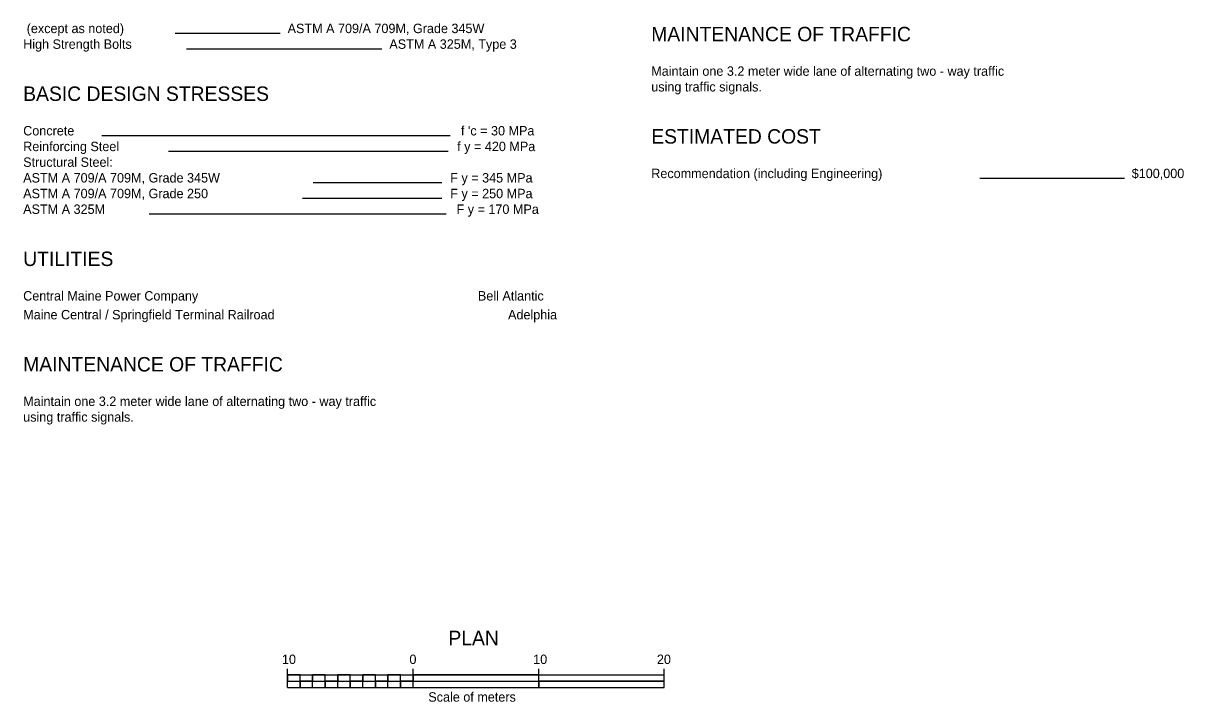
# Model space of a CAD drawing. Extents: x 605371.3 to 605398.1, y 420183.2 to 420214.1.
# Drawn here: x 605390.579 to 605390.9486, y 420198.7766 to 420198.9928 of the extents above; entities that cross this region are included whole.
import ezdxf

# ---------------------------------------------------------------- set-up
doc = ezdxf.new("R2010")
doc.units = 0
doc.layers.add('Fram_Steel', color=7, linetype='Continuous')

msp = doc.modelspace()

# ---------------------------------------------------------------- linework, layer by layer
at = {"layer": 'Fram_Steel'}
for p, q in [((605390.62737, 420198.9896), (605390.66085, 420198.9896)), ((605390.62737, 420198.9896), (605390.66085, 420198.9896)), ((605390.63099, 420198.9846), (605390.6932, 420198.9846)), ((605390.63099, 420198.9846), (605390.6932, 420198.9846)), ((605390.60403, 420198.957), (605390.71501, 420198.957)), ((605390.60403, 420198.957), (605390.71501, 420198.957)), ((605390.62523, 420198.952), (605390.71437, 420198.952)), ((605390.62523, 420198.952), (605390.71437, 420198.952)), ((605390.88363, 420198.9434), (605390.92966, 420198.9434)), ((605390.88363, 420198.9434), (605390.92966, 420198.9434)), ((605390.67134, 420198.942), (605390.71227, 420198.942)), ((605390.67134, 420198.942), (605390.71227, 420198.942)), ((605390.66793, 420198.937), (605390.71227, 420198.937)), ((605390.66793, 420198.937), (605390.71227, 420198.937)), ((605390.61914, 420198.932), (605390.71372, 420198.932)), ((605390.61914, 420198.932), (605390.71372, 420198.932)), ((605390.66316, 420198.78111), (605390.66316, 420198.78711)), ((605390.66316, 420198.78111), (605390.66316, 420198.78711)), ((605390.66716, 420198.78511), (605390.66316, 420198.78511)), ((605390.66316, 420198.78511), (605390.66316, 420198.78311)), ((605390.66316, 420198.78511), (605390.78316, 420198.78511)), ((605390.66316, 420198.78511), (605390.78316, 420198.78511)), ((605390.66716, 420198.78311), (605390.66716, 420198.78511)), ((605390.66716, 420198.78111), (605390.66716, 420198.78511)), ((605390.66716, 420198.78111), (605390.66716, 420198.78511)), ((605390.67516, 420198.78511), (605390.67116, 420198.78511)), ((605390.67116, 420198.78511), (605390.67116, 420198.78311)), ((605390.67116, 420198.78111), (605390.67116, 420198.78511)), ((605390.67116, 420198.78111), (605390.67116, 420198.78511)), ((605390.67516, 420198.78311), (605390.67516, 420198.78511)), ((605390.67516, 420198.78111), (605390.67516, 420198.78511)), ((605390.67516, 420198.78111), (605390.67516, 420198.78511)), ((605390.68316, 420198.78511), (605390.67916, 420198.78511)), ((605390.67916, 420198.78511), (605390.67916, 420198.78311)), ((605390.67916, 420198.78111), (605390.67916, 420198.78511)), ((605390.67916, 420198.78111), (605390.67916, 420198.78511)), ((605390.68316, 420198.78311), (605390.68316, 420198.78511)), ((605390.68316, 420198.78111), (605390.68316, 420198.78511)), ((605390.68316, 420198.78111), (605390.68316, 420198.78511)), ((605390.69116, 420198.78511), (605390.68716, 420198.78511)), ((605390.68716, 420198.78511), (605390.68716, 420198.78311)), ((605390.68716, 420198.78111), (605390.68716, 420198.78511)), ((605390.68716, 420198.78111), (605390.68716, 420198.78511)), ((605390.69116, 420198.78311), (605390.69116, 420198.78511)), ((605390.69116, 420198.78111), (605390.69116, 420198.78511)), ((605390.69116, 420198.78111), (605390.69116, 420198.78511)), ((605390.69916, 420198.78511), (605390.69516, 420198.78511)), ((605390.69516, 420198.78511), (605390.69516, 420198.78311)), ((605390.69516, 420198.78111), (605390.69516, 420198.78511)), ((605390.69516, 420198.78111), (605390.69516, 420198.78511)), ((605390.69916, 420198.78311), (605390.69916, 420198.78511)), ((605390.69916, 420198.78111), (605390.69916, 420198.78511)), ((605390.69916, 420198.78111), (605390.69916, 420198.78511)), ((605390.70316, 420198.78111), (605390.70316, 420198.78711)), ((605390.70316, 420198.78111), (605390.70316, 420198.78711)), ((605390.74316, 420198.78511), (605390.70316, 420198.78511)), ((605390.70316, 420198.78511), (605390.70316, 420198.78311)), ((605390.74316, 420198.78111), (605390.74316, 420198.78711)), ((605390.74316, 420198.78111), (605390.74316, 420198.78711)), ((605390.74316, 420198.78311), (605390.74316, 420198.78511)), ((605390.78316, 420198.78111), (605390.78316, 420198.78711)), ((605390.78316, 420198.78111), (605390.78316, 420198.78711)), ((605390.66316, 420198.78311), (605390.66716, 420198.78311)), ((605390.66316, 420198.78311), (605390.78316, 420198.78311)), ((605390.66316, 420198.78311), (605390.78316, 420198.78311)), ((605390.66316, 420198.78111), (605390.78316, 420198.78111)), ((605390.66316, 420198.78111), (605390.78316, 420198.78111)), ((605390.67116, 420198.78311), (605390.66716, 420198.78311)), ((605390.66716, 420198.78311), (605390.66716, 420198.78111)), ((605390.66716, 420198.78111), (605390.67116, 420198.78111)), ((605390.67116, 420198.78111), (605390.67116, 420198.78311)), ((605390.67116, 420198.78311), (605390.67516, 420198.78311)), ((605390.67916, 420198.78311), (605390.67516, 420198.78311)), ((605390.67516, 420198.78311), (605390.67516, 420198.78111)), ((605390.67516, 420198.78111), (605390.67916, 420198.78111)), ((605390.67916, 420198.78111), (605390.67916, 420198.78311)), ((605390.67916, 420198.78311), (605390.68316, 420198.78311)), ((605390.68716, 420198.78311), (605390.68316, 420198.78311)), ((605390.68316, 420198.78311), (605390.68316, 420198.78111)), ((605390.68316, 420198.78111), (605390.68716, 420198.78111)), ((605390.68716, 420198.78111), (605390.68716, 420198.78311)), ((605390.68716, 420198.78311), (605390.69116, 420198.78311)), ((605390.69516, 420198.78311), (605390.69116, 420198.78311)), ((605390.69116, 420198.78311), (605390.69116, 420198.78111)), ((605390.69116, 420198.78111), (605390.69516, 420198.78111)), ((605390.69516, 420198.78111), (605390.69516, 420198.78311)), ((605390.69516, 420198.78311), (605390.69916, 420198.78311)), ((605390.70316, 420198.78311), (605390.69916, 420198.78311)), ((605390.69916, 420198.78311), (605390.69916, 420198.78111)), ((605390.69916, 420198.78111), (605390.70316, 420198.78111)), ((605390.70316, 420198.78111), (605390.70316, 420198.78311)), ((605390.70316, 420198.78311), (605390.74316, 420198.78311)), ((605390.78316, 420198.78311), (605390.74316, 420198.78311)), ((605390.74316, 420198.78311), (605390.74316, 420198.78111)), ((605390.74316, 420198.78111), (605390.78316, 420198.78111)), ((605390.78316, 420198.78111), (605390.78316, 420198.78311))]:
    msp.add_line(p, q, dxfattribs=at)

# ---------------------------------------------------------------- texts
for s, height, p in [(' (except as noted)', 0.003, (605390.579, 420198.9896)), (' (except as noted)', 0.003, (605390.579, 420198.9896)), ('ASTM A 709/A 709M, Grade 345W', 0.003, (605390.6632, 420198.9896)), ('ASTM A 709/A 709M, Grade 345W', 0.003, (605390.6632, 420198.9896)), ('MAINTENANCE OF TRAFFIC', 0.0045996, (605390.779, 420198.987)), ('MAINTENANCE OF TRAFFIC', 0.0045996, (605390.779, 420198.987)), ('High Strength Bolts', 0.003, (605390.579, 420198.9846)), ('High Strength Bolts', 0.003, (605390.579, 420198.9846)), ('ASTM A 325M, Type 3', 0.003, (605390.6956, 420198.9846)), ('ASTM A 325M, Type 3', 0.003, (605390.6956, 420198.9846)), ('Maintain one 3.2 meter wide lane of alternating two - way traffic', 0.003, (605390.779, 420198.976)), ('Maintain one 3.2 meter wide lane of alternating two - way traffic', 0.003, (605390.779, 420198.976)), ('BASIC DESIGN STRESSES', 0.0045996, (605390.579, 420198.968)), ('BASIC DESIGN STRESSES', 0.0045996, (605390.579, 420198.968)), ('using traffic signals.', 0.003, (605390.779, 420198.971)), ('using traffic signals.', 0.003, (605390.779, 420198.971)), ('Concrete', 0.003, (605390.579, 420198.957)), ('Concrete', 0.003, (605390.579, 420198.957)), ("f 'c = 30 MPa", 0.003, (605390.7184, 420198.957)), ("f 'c = 30 MPa", 0.003, (605390.7184, 420198.957)), ('ESTIMATED COST', 0.0045996, (605390.779, 420198.9544)), ('ESTIMATED COST', 0.0045996, (605390.779, 420198.9544)), ('Reinforcing Steel', 0.003, (605390.579, 420198.952)), ('Reinforcing Steel', 0.003, (605390.579, 420198.952)), ('f y = 420 MPa', 0.003, (605390.7172, 420198.952)), ('f y = 420 MPa', 0.003, (605390.7172, 420198.952)), ('Structural Steel:', 0.003, (605390.579, 420198.947)), ('Structural Steel:', 0.003, (605390.579, 420198.947)), ('$100,000', 0.003, (605390.932, 420198.9434)), ('$100,000', 0.003, (605390.932, 420198.9434)), ('ASTM A 709/A 709M, Grade 345W', 0.003, (605390.579, 420198.942)), ('ASTM A 709/A 709M, Grade 345W', 0.003, (605390.579, 420198.942)), ('F y = 345 MPa', 0.003, (605390.715, 420198.942)), ('F y = 345 MPa', 0.003, (605390.715, 420198.942)), ('Recommendation (including Engineering)', 0.003, (605390.779, 420198.9434)), ('Recommendation (including Engineering)', 0.003, (605390.779, 420198.9434)), ('ASTM A 709/A 709M, Grade 250', 0.003, (605390.579, 420198.937)), ('ASTM A 709/A 709M, Grade 250', 0.003, (605390.579, 420198.937)), ('F y = 250 MPa', 0.003, (605390.715, 420198.937)), ('F y = 250 MPa', 0.003, (605390.715, 420198.937)), ('ASTM A 325M', 0.003, (605390.579, 420198.932)), ('ASTM A 325M', 0.003, (605390.579, 420198.932)), ('F y = 170 MPa', 0.003, (605390.717, 420198.932)), ('F y = 170 MPa', 0.003, (605390.717, 420198.932)), ('UTILITIES', 0.0046, (605390.579, 420198.9154)), ('UTILITIES', 0.0046, (605390.579, 420198.9154)), ('Central Maine Power Company', 0.003, (605390.579, 420198.9044)), ('Central Maine Power Company', 0.003, (605390.579, 420198.9044)), ('Bell Atlantic', 0.003, (605390.7238, 420198.9044)), ('Bell Atlantic', 0.003, (605390.7238, 420198.9044)), ('Maine Central / Springfield Terminal Railroad', 0.003, (605390.579, 420198.8984)), ('Maine Central / Springfield Terminal Railroad', 0.003, (605390.579, 420198.8984)), ('Adelphia', 0.003, (605390.7334, 420198.8984)), ('Adelphia', 0.003, (605390.7334, 420198.8984)), ('MAINTENANCE OF TRAFFIC', 0.0045996, (605390.579, 420198.8818)), ('MAINTENANCE OF TRAFFIC', 0.0045996, (605390.579, 420198.8818)), ('Maintain one 3.2 meter wide lane of alternating two - way traffic', 0.003, (605390.579, 420198.8708)), ('Maintain one 3.2 meter wide lane of alternating two - way traffic', 0.003, (605390.579, 420198.8708)), ('using traffic signals.', 0.003, (605390.579, 420198.8658)), ('using traffic signals.', 0.003, (605390.579, 420198.8658)), ('PLAN', 0.0046, (605390.7144, 420198.7946)), ('PLAN', 0.0046, (605390.7144, 420198.7946)), ('10', 0.003, (605390.6614, 420198.7886)), ('10', 0.003, (605390.6614, 420198.7886)), ('0', 0.003, (605390.702, 420198.7886)), ('0', 0.003, (605390.702, 420198.7886)), ('10', 0.003, (605390.7414, 420198.7886)), ('10', 0.003, (605390.7414, 420198.7886)), ('20', 0.003, (605390.7808, 420198.7886)), ('20', 0.003, (605390.7808, 420198.7886)), ('Scale of meters', 0.003, (605390.708, 420198.7766)), ('Scale of meters', 0.003, (605390.708, 420198.7766))]:
    msp.add_text(s, height=height, dxfattribs=at).set_placement(p)

doc.saveas('drawing.dxf')
